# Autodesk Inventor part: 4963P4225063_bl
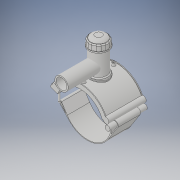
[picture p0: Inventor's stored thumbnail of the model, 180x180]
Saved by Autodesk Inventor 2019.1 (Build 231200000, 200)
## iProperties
Created: 2017-07
Part Number: 4963P4225063_bl
Material: Generic
Document SubType Name: Modeling
Designer: KIM
Density: 1 g/cm^3
Appearance: Default
Author: KIM
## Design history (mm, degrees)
derived "4963P4.ipt"
feature "Solid1::4963P4.ipt" dims "ScaleForDerivedMember" = 10
feature "Solid2::4963P4.ipt" dims "ScaleForDerivedMember" = 10
feature "Solid3::4963P4.ipt" dims "ScaleForDerivedMember" = 10
tag "TaggingFeature1"
body "Solid1"
body "Solid2"
body "Solid3"
other parameters: "d0" = 225 [user parameter], "d2" = 295.1 [user parameter], "d3" = 56.25 [user parameter], "d4" = 176 [user parameter], "d5" = 0 [user parameter], "d6" = 0.1 [user parameter], "d8" = 0 [user parameter], "d19" = 6 [user parameter], "d20" = 6 [user parameter], "d21" = 105.6 [user parameter], "d23" = 0 [user parameter], "d24" = 52.8 [user parameter], "d26" = 0 [user parameter], "d27" = 3 [user parameter], "d28" = 3 [user parameter], "d29" = 3 [user parameter], "d30" = 75 [user parameter], "d31" = 6 [user parameter], "d32" = 0 [user parameter], "d33" = 0 [user parameter], "d34" = 0.6 [user parameter], "d40" = 135.72 [user parameter], "d43" = 0 [user parameter], "d45" = 0 [user parameter], "d47" = 236.1 [user parameter], "d70" = 15 [user parameter], "d72" = 0 [user parameter], "d73" = 6 [user parameter], "d75" = 5 [user parameter], "d76" = 0 [user parameter], "d77" = 11.25 [user parameter], "d78" = 142.5 [user parameter], "d79" = 15 [user parameter], "d80" = 70.4 [user parameter], "d82" = 5 deg [user parameter], "d84" = 4 [user parameter], "d85" = 14 [user parameter], "d86" = 0 [user parameter], "d87" = 3 [user parameter], "d88" = 0 [user parameter], "d89" = 1 [user parameter], "d90" = 1 [user parameter], "d91" = 140.8 [user parameter], "d92" = 0 [user parameter], "d93" = 0.5 [user parameter], "d94" = 118.42105 [user parameter], "d96" = 266.22 [user parameter], "d97" = 3.52 [user parameter], "d98" = 0 [user parameter], "d102" = 2.25 [user parameter], "d120" = 140 deg [user parameter], "d121" = 24.228 [user parameter], "d122" = 20 deg [user parameter], "d123" = 522 [user parameter], "d124" = 156.6 [user parameter], "d126" = 0 [user parameter], "d143" = 231.75 [user parameter], "d145" = 27.69231 [user parameter], "d149" = 3.375 [user parameter], "d150" = 30.46154 [user parameter], "d153" = 176 [user parameter], "d154" = 0 [user parameter], "d156" = 130.5 [user parameter], "d157" = 160 deg [user parameter], "d159" = 7.2 [user parameter], "d161" = 3.375 [user parameter], "d162" = 105.6 [user parameter], "d163" = 0 [user parameter], "d164" = 112.5 [user parameter], "d167" = 22.5 [user parameter], "d168" = 127.31707 [user parameter], "d170" = 3.375 [user parameter], "d172" = 0 [user parameter], "d173" = 1 [user parameter], "d175" = 112.5 [user parameter], "d176" = 20 deg [user parameter], "d177" = 15.75 [user parameter], "d178" = 36 [user parameter], "d180" = 0 [user parameter], "d183" = 14.4 [user parameter], "d184" = 12.6 [user parameter], "d185" = 57.2 [user parameter], "d186" = 57.2 [user parameter], "d187" = 130.5 [user parameter], "d188" = 10.8 [user parameter], "d189" = 15.75 [user parameter], "d190" = 0 [user parameter], "d191" = 195.75 [user parameter], "d193" = 7.2 [user parameter], "d194" = 6.16 [user parameter], "d195" = 90 deg [user parameter], "d197" = 0 [user parameter], "d199" = 0 [user parameter], "d200" = 18 [user parameter], "d202" = 0 [user parameter], "d203" = 177 [user parameter], "d204" = 85.5 [user parameter], "d205" = 63 [user parameter], "d206" = 76.5 [user parameter], "d207" = 132.75 [user parameter], "d208" = 138.06 [user parameter], "d209" = 164.61 [user parameter], "d210" = 77.4 [user parameter], "d212" = 72 [user parameter], "d213" = 29.25 [user parameter], "d216" = 0 [user parameter], "d217" = 22.5 [user parameter], "d218" = 22.5 [user parameter], "d219" = 4.5 [user parameter], "d222" = 225 [user parameter], "d224" = 0 [user parameter], "d225" = 64 [user parameter], "d226" = 63 [user parameter], "d227" = 50.4 [user parameter], "d228" = 175 [user parameter], "d230" = 4.5 [user parameter], "d_" = 225 [user parameter], "B_" = 227 [user parameter], "L_" = 176 [user parameter], "d_t" = 6 [user parameter]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
